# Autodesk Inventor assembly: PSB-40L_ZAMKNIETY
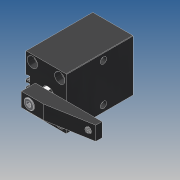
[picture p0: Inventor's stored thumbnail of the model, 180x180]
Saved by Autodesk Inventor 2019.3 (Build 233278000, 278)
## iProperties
Company: Î¢ÈíÖÐ¹ú
Created: 2013-10
Part Number: PSB-40L_ZAMKNIETY
Material: Ogólny
Description: STEP AP203
Document SubType Name: Assembly
Designer: CADENGINEERING4
Sending System: SolidWorks 2012
Preprocessor: SwSTEP 2.0
Title: PSB-40.STEP
Author: Î¢ÈíÓÃ»§
Revision Number: ÈÎºÎ
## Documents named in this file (6)
- E:\SERWER_ZAPAS\Pneumatic\PSB PNEUMATIC SWING\PSB-40\PSB-40L_ZAMKNIETY.iam
- E:\SERWER_ZAPAS\Pneumatic\PSB PNEUMATIC SWING\PSB-40\PSB40BT.ipt
- E:\SERWER_ZAPAS\Pneumatic\PSB PNEUMATIC SWING\PSB-40\PSB40HSG.ipt
- E:\SERWER_ZAPAS\Pneumatic\PSB PNEUMATIC SWING\PSB-40\PSB40YB.ipt
- E:\SERWER_ZAPAS\Pneumatic\PSB PNEUMATIC SWING\PSB-40\PSB40HG.ipt
- E:\SERWER_ZAPAS\Pneumatic\PSB PNEUMATIC SWING\PSB-40\socket head cap screw_iso_ISO 4762 M8 x 25 --- 25S.ipt
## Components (5 placed, 5 different names)
1. PSB40BT_1 — Zestawiające:1, Kątowe:1
2. PSB40HSG_2 — Zestawiające:1, Zestawiające:2, Zestawiające:3, Zestawiające:4
3. PSB40YB_3 — Zestawiające:3, Zestawiające:4, Zestawiające:5, Zestawiające:6, Kątowe:1
4. PSB40HG_4 — Zestawiające:2
5. socket head cap screw_iso_ISO 4762 M8 x 25 --- 25S_5 — Zestawiające:5, Zestawiające:6
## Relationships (7: Mate 6, Angle 1)
- Zestawiające:1 [Mate]: PSB40BT_1 ↔ PSB40HSG_2
- Zestawiające:2 [Mate]: PSB40HSG_2 ↔ PSB40HG_4
- Zestawiające:3 [Mate]: PSB40HSG_2 ↔ PSB40YB_3
- Zestawiające:4 [Mate]: PSB40HSG_2 ↔ PSB40YB_3
- Zestawiające:5 [Mate]: PSB40YB_3 ↔ socket head cap screw_iso_ISO 4762 M8 x 25 --- 25S_5
- Zestawiające:6 [Mate]: PSB40YB_3 ↔ socket head cap screw_iso_ISO 4762 M8 x 25 --- 25S_5
- Kątowe:1 [Angle]: PSB40BT_1 ↔ PSB40YB_3
